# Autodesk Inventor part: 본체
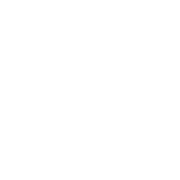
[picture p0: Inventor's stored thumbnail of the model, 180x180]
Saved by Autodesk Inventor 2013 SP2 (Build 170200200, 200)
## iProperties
Created: 2024-08
Part Number: 본체
Material: Generic
Document SubType Name: 판금
Designer: a
Density: 1 g/cm^3
Sheet Metal Rule: 기본값
Author: a
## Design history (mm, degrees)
sketch "스케치21"
  geometry: 1 further point
node "솔리드4"
other parameters: "K계수" = 4.4, "BendRadius" = 3.048 (derived), "BendReliefWidth" = 3.048 (derived), "BendReliefDepth" = 1.524 (derived), "CornerReliefSize" = 12.192 (derived), "SeamGap" = 0.00508, "MinimumRemnant" = 6.096 (derived), "TransitionRadius" = 3.048 (= BendRadius)
